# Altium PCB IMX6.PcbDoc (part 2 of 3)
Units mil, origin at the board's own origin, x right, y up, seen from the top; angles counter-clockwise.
Board outline 7950 x 5550 mil, 4 copper layers (Top Layer, GND, VCC, Bottom Layer), stack 30.634 mil thick; 238 components, 319 nets, 1015 pads, 404 vias.
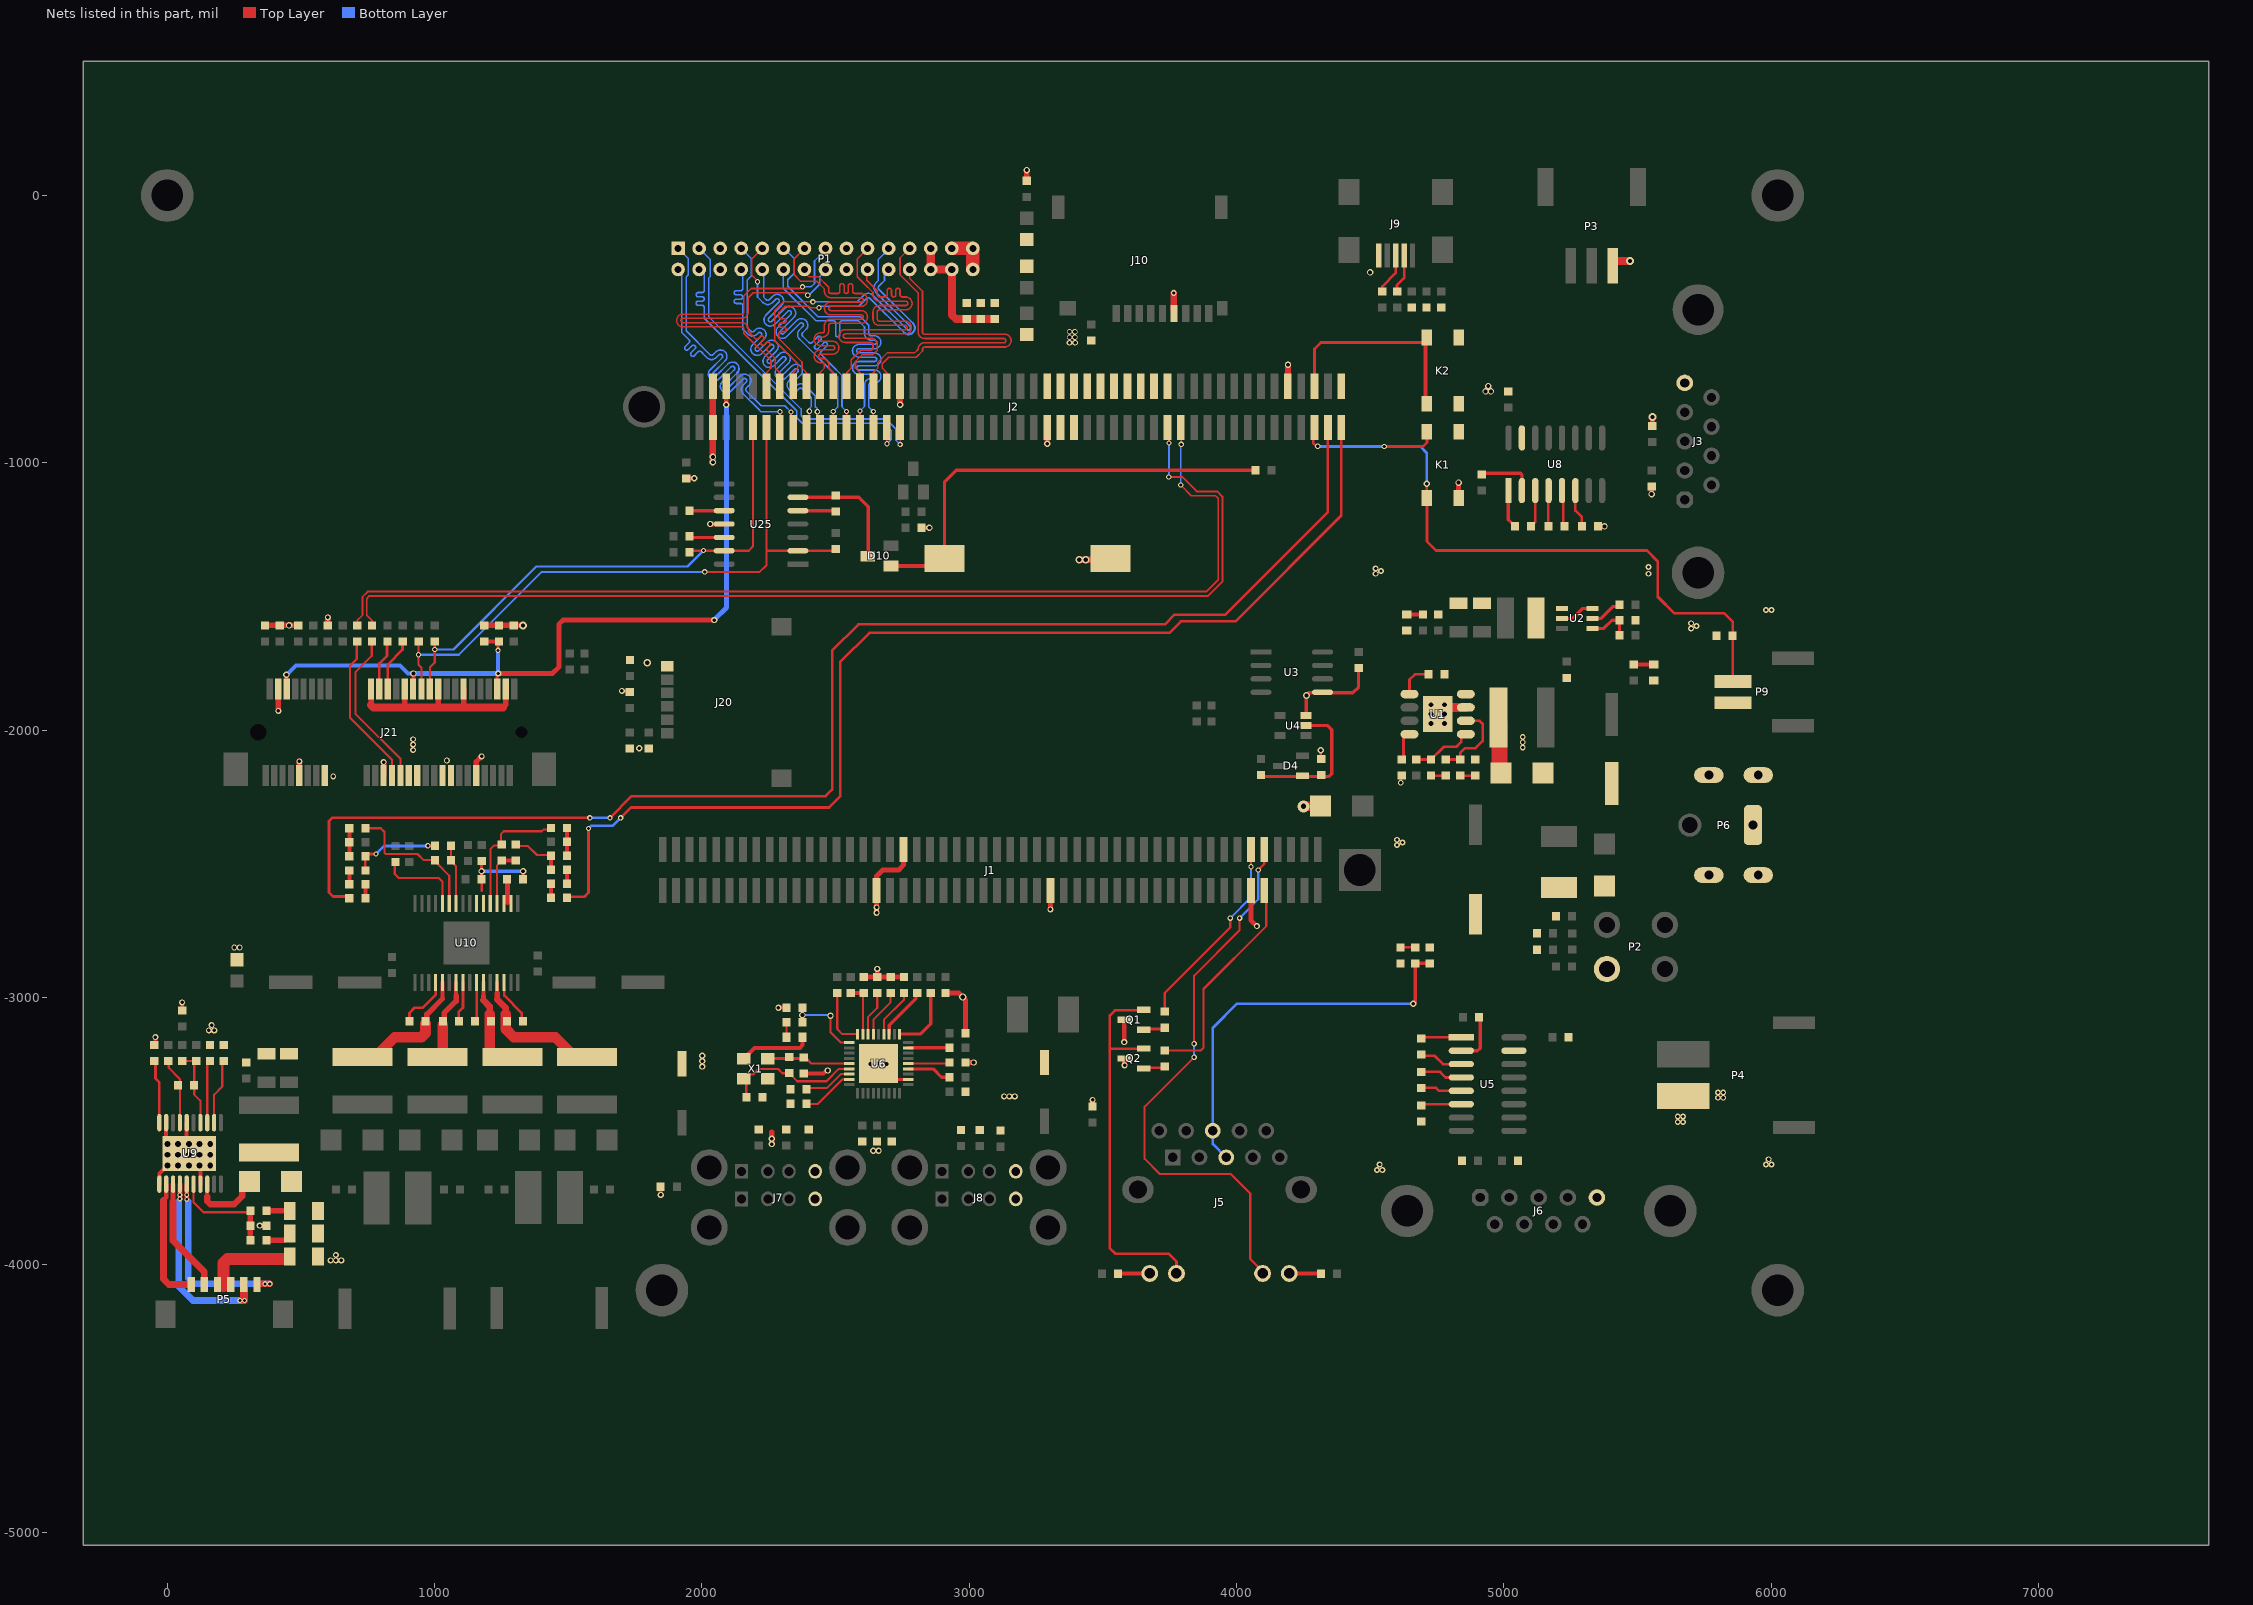
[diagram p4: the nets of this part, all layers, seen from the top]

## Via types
v1: diameter 20, hole 12, Top Layer to Bottom Layer, 138 vias
v2: diameter 22, hole 14, Top Layer to Bottom Layer, 54 vias
v3: diameter 24, hole 14, Top Layer to Bottom Layer, 53 vias
v4: diameter 22, hole 12, Top Layer to Bottom Layer, 39 vias
v5: diameter 23, hole 13, Top Layer to Bottom Layer, 38 vias
v6: diameter 22, hole 13, Top Layer to Bottom Layer, 21 vias
v7: diameter 30, hole 22, Top Layer to Bottom Layer, tented top, 15 vias
v8: diameter 22, hole 18, Top Layer to Bottom Layer, 6 vias
v9: diameter 25, hole 16, Top Layer to Bottom Layer, 5 vias
v10: diameter 24, hole 13, Top Layer to Bottom Layer, 5 vias
v11: diameter 20, hole 15, Top Layer to Bottom Layer, 5 vias
v12: diameter 30, hole 15, Top Layer to Bottom Layer, 4 vias
v13: diameter 18, hole 10, Top Layer to Bottom Layer, 4 vias
v14: diameter 20, hole 14, Top Layer to Bottom Layer, 4 vias
v15: diameter 28, hole 16, Top Layer to Bottom Layer, 3 vias
v16: diameter 26, hole 15, Top Layer to Bottom Layer, 3 vias
v17: diameter 45, hole 20, Top Layer to Bottom Layer, 1 vias
v18: diameter 28, hole 17, Top Layer to Bottom Layer, 1 vias
v19: diameter 25, hole 15, Top Layer to Bottom Layer, 1 vias
v20: diameter 28, hole 15, Top Layer to Bottom Layer, 1 vias
v21: diameter 18, hole 12, Top Layer to Bottom Layer, 1 vias
v22: diameter 30, hole 16, Top Layer to Bottom Layer, 1 vias
v23: diameter 25, hole 14, Top Layer to Bottom Layer, 1 vias

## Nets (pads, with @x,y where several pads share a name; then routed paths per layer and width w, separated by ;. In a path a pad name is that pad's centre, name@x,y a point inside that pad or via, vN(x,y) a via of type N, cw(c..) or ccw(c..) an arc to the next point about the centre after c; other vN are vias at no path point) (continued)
GND: BT1.2 C1.2 C2.2 C3.2 C5.2 C8.2 C10.1 C17.2 C18.2 C19.2 C20.1 C22.1 C23.2 C27.2 C29.2 C30.1 C31.1 C32.1 C34.1 C35.1 C36.2 C37.1 C38.1 C39.1 C40.1 C41.1 C42.1 C43.1 C44.1 C45.1 C46.1 C47.1 C48.1 C49.1 C50.1 C52.2 C53.1 C54.1 C55.2 C57.2 C58.1 C59.1 C60.1 C61.1 C62.1 C64.1 C86.2 C87.2 C88.2 C109.2 C110.2 C111.2 C112.2 C113.2 D1.A D3.K D5.K D7.A D8.K D16.1 D17.1 D18.2 D19.2 D20.2 D21.2 D22.2 D23.1 D24.2 D25.1 D26.2 D27.1 D28.2 D29.1 D30.1 D31.2 D32.2 D33.1 J1.33 J1.38 J1.59 J1.89 J2.5 J2.6 J2.34 J2.55 J2.92 J3.5 J6.5 J7.4 J7.8 J8.4 J8.8 J9.5 J10.6 J20.1 J21.4 J21.9 J21.15 J21.18 J21.21 J21.26 J21.27 J21.29 J21.34 J21.35 J21.37 J21.40 J21.43 J21.50 K1.1 K1.2 K2.1 K2.2 L2.1 L3.1 P1.5 P1.6 P1.17 P1.18 P1.25 P1.26 P1.28 P2.2 P3.3 P4.2 P6.1 P9.2 Q1.3 Q2.3 R1.1 R5.1 R15.2 R25.2 R26.2 R27.2 R28.1 R30.2 R37.1 R39.1 R43.2 R59.1 R87.1 R88.1 U1.7 U1.9 U2.1 U3.5 U4.3 U5.15 U6.11 U6.37 U8.15 U9.6 U9.9 U9.11 U9.17 U9.21 U25.11 X1.2 X1.4 | length 5501.4
  Top Layer w10: C22.1@4315,-2107 v3(4315,-2075) ; v1@4614,-2194 C8.2@4614,-2170 ; R1.1@4727,-2170 C10.1@4782,-2170
  Top Layer w12: C32.1@56,-3048 v5(56,-3018) ; v5(1701,-1853) 1733.71,-1853 1733.8,-1852.91 D32.2@1730.09,-1852.91 ; U6.37@2720.05,-3306.15 U6.11@2771.24,-3306.15 ; U4.3@4259.23,-1945.6 4260,-1944.83 4260,-1870 4270,-1860 4435,-1860 4456,-1839 C2.2@4456,-1768
  Top Layer w15: R43.2@-44,-3178 v5(-44,-3148) ; U9.11@-29.32,-3698 -29.32,-3658.32 U9.21@-14,-3643 ; U9.21@-3.72,-3528 U9.9@-3.72,-3468 ; U9.21@73.05,-3573.16 U9.6@73.05,-3468 ; U9.17@124.23,-3698 U9.21@124.23,-3624.34 ; v5(346,-3853) R37.1@371,-3853 ; v5(1846,-3738) C30.1@1846,-3708 ; X1.4@2156,-3228.2 2196.2,-3188 2366,-3188 2376,-3178 D5.K@2376,-3148 ; v5(2286,-3038) R30.2@2316,-3038 ; C39.1@2381,-3283.52 2455.48,-3283.52 2466,-3273 v3(2471,-3273)
  Top Layer w18: C18.2@1941,-1058 v3(1971,-1058) ; v3(2031,-1229) U25.11@2083.41,-1229 ; C31.1@2606,-2923 R25.2@2656,-2923 ; v5(2653.52,-2683) 2653.52,-2545.48 2676,-2523 2736,-2523 2753.52,-2505.48 J1.38@2753.52,-2446.23 ; v5(2656,-2893) R25.2@2656,-2923 ; R27.2@2756,-2923 R26.2@2706,-2923 R25.2@2656,-2923 ; C40.1@2821,-1243 v3(2851,-1243) ; C23.2@2911,-2983 2961,-2983 2986,-3008 C109.2@2986,-3133 ; C46.1@2986,-3243 v3(3016,-3243) ; v5(3303.52,-2670.52) J1.59@3303.52,-2599.77 ; C37.1@3461,-3408 v5(3461,-3383) ; v5(3579.58,-3166.58) Q1.3@3579.58,-3083 ; v5(3581,-3253) Q2.3@3581,-3229.42 ; J1.89@4053.52,-2599.77 4053.52,-2710.52 v5(4076,-2733) ; K1.2@4830.05,-1127.02 v3(4830.05,-1073.95) ; C55.2@5351,-1238 v3(5376,-1238) ; v3(5551.91,-1117.09) D18.2@5551.91,-1088.09 ; D19.2@5555.09,-862.91 v12@5555.09,-829
  Top Layer w20: C44.1@366,-1608 C50.1@421,-1608 R87.1@491,-1608 ; v5(415.8,-1927.8) J21.4@415.8,-1846.58 ; J21.9@494.54,-2169.42 v6(494.54,-2116.54) ; R88.1@601,-1608 v6(601,-1578) ; 762.72,-1906.72 J21.18@762.72,-1849.58 ; J21.21@809.5,-2171.5 v6(809.5,-2119.42) ; 888.72,-1918.72 J21.26@888.72,-1858.58 ; 1013.72,-1916.72 J21.34@1013.72,-1856.58 ; 1108.72,-1906.72 J21.40@1108.72,-1846.58 ; J21.43@1155.96,-2169.42 1155.96,-2118.04 v6(1176,-2098) ; C112.2@1186,-1608 C113.2@1241,-1608 C43.1@1296,-1608 v12(1331,-1608) ; 1256,-1916 1266,-1906 J21.50@1266,-1846.78 ; v5(2261,-3548) 2261,-3503 ; C111.2@3215,68 v3(3215,95) ; v3(3291.31,-928.51) J2.55@3291.31,-867.49
  Top Layer w22: v3(2741.31,-782.69) J2.34@2741.31,-713.94 ; J2.92@4191.31,-713.94 v3(4192,-633)
  Top Layer w24: v3(2041.31,-998.31) J2.6@2041.31,-713.94 ; v15(3411,-1363) BT1.2@3524.03,-1363
  Top Layer w25: J10.6@3765,-425 v4(3765,-365)
  Top Layer w30: 762.72,-1906.72 772,-1916 1256,-1916 ; P1.25@2855.88,-198 P1.26@2855.88,-276.74 P1.28@2934.62,-276.74 2934.62,-446.62 2951,-463 C52.2@2991,-463 C53.1@3043,-463 C54.1@3096,-463 ; D7.A@5145,-2160 D7.A@5145.74,-2160 ; P2.2@5385,-2895 P2.2@5385,-2893.35 ; P3.3@5424.48,-246 v12(5472,-246)
  Top Layer w35: v17@4250,-2284 D1.A@4314.26,-2284 ; U1.9@4777,-1915 U1.7@4857.31,-1915
  other v1: 4614,-2197
  other v2: 251,-2813 271,-2813 1046,-2113
  other v3: 1766,-2068 2041.31,-978 4931,-733 4951,-733 4941,-713 4499,-288
  other v4: 4525,-3645 4545,-3645 4535,-3625 5980,-3625 6000,-3625 5990,-3605 5650,-3465 5670,-3465 5650,-3445 5670,-3445 5800,-3375 5820,-3375 5800,-3355 5820,-3355 4600,-2430 4620,-2420 4600,-2410 920,-2074 5070,-2065 920,-2054 5070,-2045 920,-2034 5070,-2025 5700,-1620 5720,-1610 5700,-1600 5980,-1550 6000,-1550 4520,-1415 5540,-1415 4540,-1405 4520,-1395 5540,-1390 3375,-551 3396,-551
  other v5: 611,-3983 631,-3983 651,-3983 631,-3963 2641,-3573 2661,-3573 2261,-3528 3130,-3370 3150,-3370 3170,-3370 2001,-3258 2001,-3238 2001,-3218 156,-3123 176,-3123 166,-3103 2653.52,-2663
  other v6: 621,-2173
  other v7: 1,-3628 41,-3628 81,-3628 121,-3628 161,-3628 1,-3588 41,-3588 81,-3588 121,-3588 161,-3588 1,-3548 41,-3548 81,-3548 121,-3548 161,-3548
  other v8: 4727,-1975 4777,-1975 4727,-1940 4777,-1940 4727,-1905 4777,-1905
  other v12: 5555,-829
  other v14: 3375,-530 3395,-530 3375,-510 3395,-510
  other v15: 1796,-1748 3436,-1363
  other v16: 2631,-3248 2691,-3248 2661,-3247.09
  other v17: 4250,-2285
  other v18: 2976,-2998
  other v19: 456,-1608
  other v23: 4261,-1870
GVDD: C73.2 R45.1 R49.2 U10.6 U10.7 | length 289
  Top Layer w10: 1176,-2600.95 R49.2@1176,-2568 ; R49.2@1176.95,-2557.96 R49.2@1177,-2559
  Top Layer w12: R49.2@1176,-2558 C73.2@1176,-2488 ; R45.1@1331,-2558 v3(1331,-2528)
  Bottom Layer w12: v3(1176,-2528) v3(1331,-2528)
HDMI_CEC: J2.59
HDMI_CLK_N: J2.72
HDMI_CLK_P: J2.74
HDMI_D0_N: J2.62
HDMI_D0_P: J2.60
HDMI_D1_N: J2.68
HDMI_D1_P: J2.70
HDMI_D2_N: J2.64
HDMI_D2_P: J2.66
HDMI_HPD: J2.57
HDMI_TX_DDC_SCL: J2.58
HDMI_TX_DDC_SDA: J2.56
HPL: C78.1 J2.97 | length 5188.9
  Top Layer w10: C78.1@684,-2622 620,-2622 605,-2607 605,-2340 617,-2328 v1(1581,-2328) ; v1(1656,-2328) 1737,-2247 2462,-2247 2487,-2222 2487,-1702 2585,-1604 3732,-1604 3768,-1568 3958,-1568 4341.31,-1184.69 J2.97@4341.31,-867.49
  Bottom Layer w10: v1(1581,-2328) v1(1656,-2328)
HPR: C85.1 J2.99 | length 4249.6
  Top Layer w10: C85.1@1497,-2623 1561,-2623 1576,-2608 v1(1576,-2368) ; v1(1696,-2328) 1735,-2289 2476,-2289 2518,-2247 2518,-1744 2626,-1636 3749,-1636 3792,-1593 3995,-1593 4391.31,-1196.69 J2.99@4391.31,-867.49
  Bottom Layer w10: v1(1576,-2368) 1586,-2358 1666,-2358 v1(1696,-2328)
I2C3_SCL: J2.13 J21.30 R90.2 R112.1 U25.2 | length 2391.3
  Top Layer w8: R90.2@940,-1669 940,-1755 951.24,-1766.24 J21.30@951.24,-1846.58 ; v1(2011,-1408) 2216,-1408 2241.31,-1382.69 J2.13@2241.31,-867.49 ; 2241.31,-1329 R112.1@2495,-1329
  Bottom Layer w8: v1(940,-1718) 1091,-1718 1401,-1408 v1(2011,-1408)
I2C3_SDA: J2.11 J21.32 R89.2 R113.1 U25.13 | length 2036.7
  Top Layer w8: J21.32@982.73,-1846.58 982.73,-1765.27 1001,-1747 R89.2@1001,-1667 ; R113.1@1954,-1334 1959,-1329 U25.13@2083.41,-1329 2175,-1329 2191.31,-1312.69 J2.11@2191.31,-867.49
  Bottom Layer w8: v1(1001,-1698) 1071,-1698 1381,-1388 1946,-1388 v1(2006,-1328)
LED_ACT: J1.92 J5.13 | length 2092.6
  Top Layer w8: v1(3841,-3223) 3656,-3408 3656,-3603 3713,-3660 3978,-3660 4051,-3733 4051,-3978 J5.13@4091,-4018 ; v1(3841,-3173) 3841,-2918 4011,-2748 v1(4011,-2703) ; v1(4081,-2523) 4103.52,-2500.48 J1.92@4103.52,-2446.23
  Bottom Layer w8: v1(3841,-3223) v1(3841,-3173) ; v1(4011,-2703) 4081,-2633 v1(4081,-2523)
LED_LINK10_100: J1.91 R14.2 | length 837.8
  Top Layer w8: R14.2@3731,-3198 3866,-3198 3876,-3188 3876,-2968 4111,-2733 4111,-2607.25 J1.91@4103.52,-2599.77
LED_LINK1000: J1.90 R13.2 | length 740.4
  Top Layer w8: R13.2@3731,-3053 3731,-2983 3976,-2738 v1(3976,-2703) ; v1(4053.52,-2510.48) J1.90@4053.52,-2446.23
  Bottom Layer w8: v1(3976,-2703) 4053.52,-2625.48 v1(4053.52,-2510.48)
LVDS0_CLK_N: J2.14 P1.15 | length 1285.2
  Top Layer w6: 2185,-348.37 2157,-376.37 2157,-435.69 cw(c2149,-435.69) 2149,-443.69 1929.36,-443.69 ccw(c1929.36,-467.69) 1929.36,-491.69 2149,-491.69 cw(c2149,-499.69) 2157,-499.69 2157,-515 2258.31,-616.31 2258.31,-645.7 2241.31,-662.7 J2.14@2241.31,-713.94 ; 2185,-348 2370,-348 v1(2376,-342)
  Bottom Layer w6: v1(2376,-342) 2408.37,-342 2421,-329.37 2421,-245 P1.15@2460,-206
LVDS0_CLK_P: J2.16 P1.16 | length 1267.4
  Top Layer w6: J2.16@2291.31,-713.94 2291.31,-662.7 2274.31,-645.7 2274.31,-609.69 2246.31,-581.69 2245.07,-580.44 cw(c2250.73,-574.78) 2245.07,-569.13 2252.41,-561.79 ccw(c2246.75,-556.13) 2252.41,-550.47 ccw(c2246.75,-556.13) 2241.1,-550.47 2233.75,-557.81 cw(c2228.1,-552.16) 2222.44,-557.81 cw(c2228.1,-552.16) 2222.44,-546.5 2229.78,-539.16 ccw(c2224.12,-533.5) 2229.78,-527.85 ccw(c2224.12,-533.5) 2218.47,-527.85 2211.13,-535.19 cw(c2205.47,-529.53) 2199.81,-535.19 2173,-508.37 2173,-499.69 ccw(c2149,-499.69) 2149,-475.69 1929.36,-475.69 cw(c1929.36,-467.69) 1929.36,-459.69 2149,-459.69 ccw(c2149,-435.69) 2173,-435.69 2173,-383 2191.63,-364.37 2387.37,-364.37 v1(2396,-373)
  Bottom Layer w6: v1(2396,-373) 2400,-373 2441,-332 2441,-303.63 P1.16@2447.31,-297.31
LVDS0_TX0_N: J2.30 P1.23 | length 1315.5
  Top Layer w6: J2.30@2641.31,-713.94 2641.31,-662.7 2658.31,-645.7 2658.31,-623.37 2692.69,-589 2795,-589 2809,-575 cw(c2833,-575) 2833,-551 ; P1.23@2777.14,-198 2741,-234.14 2741,-297 2765.83,-321.83 2809,-365 2809,-511 ccw(c2833,-511) 2833,-535 3128.5,-535 ; 2834,-551 3129,-551 ccw(c3129,-543) 3137,-543 ccw(c3129,-543) 3129,-535
LVDS0_TX0_P: J2.32 P1.24 | length 1220.3
  Top Layer w6: J2.32@2691.31,-713.94 2691.31,-662.7 2674.31,-645.7 2674.31,-630 2699.31,-605 2801.63,-605 2825,-581.63 ; P1.24@2777.14,-276.74 2777.14,-310.51 2825,-358.37 2825,-511 ccw(c2833,-511) 2833,-519 3131.5,-519 ; 2825,-581 2825,-575 cw(c2833,-575) 2833,-567 3132.5,-567 ccw(c3132.5,-543) 3156.5,-543 ccw(c3132.5,-543) 3132.5,-519
LVDS0_TX1_N: J2.18 P1.21 | length 1288.4
  Top Layer w6: J2.18@2341.31,-713.94 2341.31,-662.7 2358.31,-645.7 2358.31,-629.31 2272,-543 2272,-431.37 2305.37,-398 2381,-398 v1(2415,-398)
  Bottom Layer w6: v1(2415,-398) 2444,-398 2580.37,-398 2605.26,-373.11 cw(c2622.23,-390.08) 2639.2,-373.11 2766.85,-500.76 ; P1.21@2697,-203 2659,-241 2659,-319.37 2650.51,-327.86 ccw(c2667.49,-344.83) 2650.51,-361.8 2778.16,-489.44
  Bottom Layer w8: 2766.85,-500.76 ccw(c2772.5,-495.1) 2778.14,-500.78 ; 2778.16,-500.76 ccw(c2772.5,-495.1) 2780.5,-495.1 ccw(c2772.5,-495.1) 2778.16,-489.44
LVDS0_TX1_P: J2.20 P1.22 | length 1275.4
  Top Layer w6: J2.20@2391.31,-713.94 2391.31,-662.7 2374.31,-645.7 2374.31,-622.69 2288,-536.37 2288,-517 cw(c2296,-517) 2296,-509 2306.96,-509 ccw(c2306.96,-501) 2314.96,-501 ccw(c2306.96,-501) 2306.96,-493 2296,-493 cw(c2296,-485) 2288,-485 cw(c2296,-485) 2296,-477 2306.96,-477 ccw(c2306.96,-469) 2314.96,-469 ccw(c2306.96,-469) 2306.96,-461 2296,-461 cw(c2296,-453) 2288,-453 2288,-438 2312,-414 2399.89,-414 2405.89,-420 v1(2438,-420)
  Bottom Layer w6: v1(2438,-420) 2444,-414 2587,-414 2616.57,-384.43 cw(c2622.23,-390.08) 2627.89,-384.43 2755.53,-512.07 ; P1.22@2683,-289 2683,-318 2670.31,-330.69 2661.83,-339.17 ccw(c2667.49,-344.83) 2661.83,-350.49 2789.47,-478.13
  Bottom Layer w8: 2755.53,-512.07 ccw(c2772.5,-495.1) 2796.5,-495.1 ccw(c2772.5,-495.1) 2789.47,-478.13
LVDS0_TX2_N: J2.26 P1.19 | length 1333.8
  Top Layer w6: J2.26@2541.31,-713.94 2541.31,-662.7 2558.31,-645.7 2558.31,-614.37 2593.69,-579 2634,-579 2640,-573 2640,-558 ccw(c2632,-558) 2632,-550 2536.46,-550 cw(c2536.46,-526) 2536.46,-502 2759.54,-502 ccw(c2759.54,-494) 2767.54,-494 ccw(c2759.54,-494) 2759.54,-486 2664,-486 cw(c2664,-462) 2640,-462 2640,-435.69 cw(c2664,-435.69) 2664,-411.69 2762,-411.69 ccw(c2762,-403.69) 2770,-403.69 ccw(c2762,-403.69) 2762,-395.69 2664,-395.69 cw(c2664,-371.69) 2640,-371.69 2640,-363 2605,-328 2581,-304 2581,-238 P1.19@2614,-205 ; P1.19@2605,-212.66 P1.19@2619.66,-198
LVDS0_TX2_P: J2.28 P1.20 | length 1278.5
  Top Layer w6: J2.28@2591.31,-674 2591.31,-662.7 2574.31,-645.7 2574.31,-621 2600.31,-595 2640.63,-595 2656,-579.63 2656,-558 ccw(c2632,-558) 2632,-534 2536.46,-534 cw(c2536.46,-526) 2536.46,-518 2759.54,-518 ccw(c2759.54,-494) 2783.54,-494 ccw(c2759.54,-494) 2759.54,-470 2664,-470 cw(c2664,-462) 2656,-462 2656,-435.69 cw(c2664,-435.69) 2664,-427.69 2762,-427.69 ccw(c2762,-403.69) 2786,-403.69 ccw(c2762,-403.69) 2762,-379.69 2757,-379.69 2749,-379.69 cw(c2749,-371.69) 2741,-371.69 2741,-355.28 ccw(c2733,-355.28) 2733,-347.28 ccw(c2733,-355.28) 2725,-355.28 2725,-371.69 cw(c2717,-371.69) 2717,-379.69 cw(c2717,-371.69) 2709,-371.69 2709,-355.28 ccw(c2701,-355.28) 2701,-347.28 ccw(c2701,-355.28) 2693,-355.28 2693,-371.69 cw(c2685,-371.69) 2685,-379.69 2664,-379.69 cw(c2664,-371.69) 2656,-371.69 2656,-356.37 2616.31,-316.69 P1.20@2616.31,-280.09
LVDS0_TX3_N: J2.22 P1.13 | length 1316.7
  Top Layer w6: P1.13@2380,-202 2345,-237 2345,-297 2368.69,-320.69 2400.31,-320.69 2429.06,-320.69 2458.31,-349.94 2458.31,-358.63 ccw(c2482.31,-358.63) 2482.31,-382.63 2595.31,-382.63 cw(c2595.31,-390.63) 2603.31,-390.63 cw(c2595.31,-390.63) 2595.31,-398.63 2482.31,-398.63 ccw(c2482.31,-422.63) 2482.31,-446.63 2595.31,-446.63 cw(c2595.31,-454.63) 2603.31,-454.63 cw(c2595.31,-454.63) 2595.31,-462.63 2482.31,-462.63 ccw(c2482.31,-486.63) 2458.31,-486.63 2458.31,-505.7 cw(c2450.31,-505.7) 2450.31,-513.7 2443.84,-513.7 ccw(c2443.84,-537.7) 2443.84,-561.7 2488.79,-561.7 cw(c2488.79,-569.7) 2496.79,-569.7 cw(c2488.79,-569.7) 2488.79,-577.7 2443.84,-577.7 ccw(c2443.84,-601.7) 2443.84,-625.7 2450.31,-625.7 cw(c2450.31,-633.7) 2458.31,-633.7 2458.31,-645.7 2441.31,-662.7 J2.22@2441.31,-713.94
LVDS0_TX3_P: J2.24 P1.14 | length 1304.6
  Top Layer w6: P1.14@2389.31,-293.69 2400.31,-304.69 2435.69,-304.69 2474.31,-343.31 2474.31,-358.63 ccw(c2482.31,-358.63) 2482.31,-366.63 2508,-366.63 ccw(c2508,-358.63) 2516,-358.63 2516,-337.65 cw(c2524,-337.65) 2524,-329.65 cw(c2524,-337.65) 2532,-337.65 2532,-358.63 ccw(c2540,-358.63) 2540,-366.63 ccw(c2540,-358.63) 2548,-358.63 2548,-337.65 cw(c2556,-337.65) 2556,-329.65 cw(c2556,-337.65) 2564,-337.65 2564,-358.63 ccw(c2572,-358.63) 2572,-366.63 2580,-366.63 2581,-366.63 2595.31,-366.63 cw(c2595.31,-390.63) 2619.31,-390.63 cw(c2595.31,-390.63) 2595.31,-414.63 2482.31,-414.63 ccw(c2482.31,-422.63) 2482.31,-430.63 2595.31,-430.63 cw(c2595.31,-454.63) 2619.31,-454.63 cw(c2595.31,-454.63) 2595.31,-478.63 2482.31,-478.63 ccw(c2482.31,-486.63) 2474.31,-486.63 2474.31,-505.7 cw(c2450.31,-505.7) 2450.31,-529.7 2443.84,-529.7 ccw(c2443.84,-537.7) 2443.84,-545.7 2488.79,-545.7 cw(c2488.79,-569.7) 2512.79,-569.7 cw(c2488.79,-569.7) 2488.79,-593.7 2443.84,-593.7 ccw(c2443.84,-601.7) 2443.84,-609.7 2450.31,-609.7 cw(c2450.31,-633.7) 2474.31,-633.7 2474.31,-645.7 2491.31,-662.7 J2.24@2491.31,-713.94
LVDS1_CLK_N: J2.33 P1.3 | length 1300.4
  Top Layer w6: v1(2741.31,-931.31) J2.33@2741.31,-867.49 2741,-867.17 J2.33@2746,-862.17
  Bottom Layer w6: P1.3@1989.74,-198 2031,-239.26 2031,-303 2025,-309 2025,-452.37 2371,-798.37 2371,-825 2382,-836 2688.28,-836 2724.66,-872.37 2724.66,-914.66 v1(2741.31,-931.31)
LVDS1_CLK_P: J2.31 P1.4 | length 1312.2
  Top Layer w6: J2.31@2691,-867.17 J2.31@2691.31,-867.49 ; v1(2692,-928.51) 2692,-846.17 J2.31@2696,-842.17
  Bottom Layer w6: P1.4@2009,-276 2009,-339 2009,-347 2009,-355 cw(c2001,-355) 2001,-363 1986.35,-363 ccw(c1986.35,-371) 1978.35,-371 ccw(c1986.35,-371) 1986.35,-379 2001,-379 cw(c2001,-387) 2009,-387 cw(c2001,-387) 2001,-395 1986.35,-395 ccw(c1986.35,-403) 1978.35,-403 ccw(c1986.35,-403) 1986.35,-411 2001,-411 cw(c2001,-419) 2009,-419 2009,-459 2355,-805 2355,-831.63 2375.37,-852 2681.66,-852 2708.66,-879 2708.66,-911.85 v1(2692,-928.51)
LVDS1_TX0_N: J2.29 P1.11 | length 1286.8
  Top Layer w6: J2.29@2641.31,-867.49 v1(2641.31,-808)
  Bottom Layer w6: P1.11@2310,-201 2345,-236 2345,-291 2320.7,-315.3 2320.7,-340.07 2433.63,-453 2592,-453 2624.31,-485.31 2624.31,-517 ccw(c2632.31,-517) 2632.31,-525 2645.58,-525 cw(c2645.58,-549) 2669.58,-549 cw(c2645.58,-549) 2645.58,-573 2587.05,-573 ccw(c2587.05,-581) 2587.05,-589 2645.58,-589 cw(c2645.58,-613) 2669.58,-613 cw(c2645.58,-613) 2645.58,-637 2587.05,-637 ccw(c2587.05,-645) 2587.05,-653 2645.58,-653 cw(c2645.58,-677) 2669.58,-677 cw(c2645.58,-677) 2645.58,-701 2632.31,-701 ccw(c2632.31,-709) 2624.31,-709 2624.31,-791 v1(2641.31,-808)
LVDS1_TX0_P: J2.27 P1.12 | length 1295.5
  Top Layer w6: J2.27@2591,-867.17 J2.27@2591.31,-867.49 v1(2591.31,-806) v1@2591.31,-803.69
  Bottom Layer w6: P1.12@2304.7,-276.74 2304.7,-315.3 2304.7,-346.7 2427,-469 2476,-469 2484,-469 2492,-469 cw(c2492,-477) 2500,-477 2500,-520.98 ccw(c2508,-520.98) 2508,-528.98 ccw(c2508,-520.98) 2516,-520.98 2516,-477 cw(c2524,-477) 2524,-469 2532,-469 2544,-469 2585.37,-469 2608.31,-491.94 2608.31,-517 ccw(c2632.31,-517) 2632.31,-541 2645.58,-541 cw(c2645.58,-549) 2653.58,-549 cw(c2645.58,-549) 2645.58,-557 2587.05,-557 ccw(c2587.05,-581) 2587.05,-605 2645.58,-605 cw(c2645.58,-613) 2653.58,-613 cw(c2645.58,-613) 2645.58,-621 2587.05,-621 ccw(c2587.05,-645) 2587.05,-669 2645.58,-669 cw(c2645.58,-677) 2653.58,-677 cw(c2645.58,-677) 2645.58,-685 2632.31,-685 ccw(c2632.31,-709) 2608.31,-709 2608.31,-789 v1(2591.31,-806)
LVDS1_TX1_N: J2.23 P1.9 | length 1243.2
  Top Layer w6: v1(2208,-323) 2208,-319 2187,-298 2187,-236.96 P1.9@2225.96,-198 ; v1(2491,-808) 2491,-867.17 J2.23@2491.31,-867.49
  Bottom Layer w6: v1(2208,-323) 2208,-366 2208,-380 2220.69,-392.69 2229.17,-401.17 ccw(c2246.14,-384.2) 2263.11,-401.17 2275.84,-388.44 cw(c2281.5,-394.1) 2287.15,-388.44 cw(c2281.5,-394.1) 2289.5,-394.1 cw(c2281.5,-394.1) 2287.15,-399.76 2239.08,-447.83 ; 2239.07,-447.84 ccw(c2256.04,-464.81) 2273.01,-481.78 ; 2273.02,-481.77 2321.09,-433.71 cw(c2326.75,-439.36) 2332.41,-433.7 ; 2332.43,-433.72 cw(c2326.75,-439.36) 2334.75,-439.36 cw(c2326.75,-439.36) 2332.42,-445.01 2284.33,-493.09 ccw(c2301.3,-510.07) 2318.27,-527.04 2366.35,-478.95 cw(c2372.01,-484.61) 2377.64,-478.93 cw(c2372.01,-484.61) 2380.01,-484.61 cw(c2372.01,-484.61) 2377.66,-490.27 2364.94,-502.99 ccw(c2381.91,-519.97) 2364.94,-536.94 2508,-680 2508,-791 v1(2491,-808)
LVDS1_TX1_P: J2.25 P1.10 | length 1298.1
  Top Layer w6: v1(2541,-808) 2541,-867.17 J2.25@2541.31,-867.49
  Bottom Layer w6: 2232,-367.37 P1.10@2232,-278 ; 2232,-360 2232,-381.37 2240.49,-389.86 ccw(c2246.14,-384.2) 2251.8,-389.86 2264.53,-377.13 cw(c2281.5,-394.1) 2305.5,-394.1 cw(c2281.5,-394.1) 2298.47,-411.07 2250.39,-459.15 ccw(c2256.04,-464.81) 2250.38,-470.47 ; 2250.4,-470.49 ccw(c2256.04,-464.81) 2261.68,-470.49 ; 2261.71,-470.46 2309.78,-422.38 cw(c2326.75,-439.36) 2350.75,-439.36 cw(c2326.75,-439.36) 2343.72,-456.33 2295.65,-504.4 ccw(c2301.3,-510.07) 2295.64,-515.72 ; 2295.66,-515.74 ccw(c2301.3,-510.07) 2306.93,-515.74 ; 2306.96,-515.72 2355.04,-467.64 cw(c2372.01,-484.61) 2396.01,-484.61 cw(c2372.01,-484.61) 2388.98,-501.58 2376.25,-514.31 ccw(c2381.91,-519.97) 2376.25,-525.62 2400.63,-550 ccw(c2406.28,-544.34) 2411.94,-550 2433.01,-528.93 cw(c2438.67,-534.59) 2444.32,-528.93 cw(c2438.67,-534.59) 2444.32,-540.25 2423.25,-561.31 ccw(c2428.91,-566.97) 2423.25,-572.63 ccw(c2428.91,-566.97) 2434.57,-572.63 2455.64,-551.56 cw(c2461.29,-557.22) 2466.95,-551.56 cw(c2461.29,-557.22) 2466.95,-562.87 2445.88,-583.94 ccw(c2451.54,-589.6) 2445.88,-595.25 2483.81,-633.19 2524,-673.37 2524,-791 v1(2541,-808)
LVDS1_TX2_N: J2.21 P1.7 | length 1287.1
  Top Layer w6: v1(2432,-809) 2432,-858.17 J2.21@2441.31,-867.49
  Bottom Layer w6: P1.7@2153,-204 2185,-236 2185,-301 2169,-317 2169,-493.37 2183.31,-507.69 ccw(c2188.97,-502.03) 2194.63,-507.69 2199.17,-503.14 cw(c2216.14,-520.11) 2240.14,-520.11 cw(c2216.14,-520.11) 2233.11,-537.08 2201.4,-568.79 ccw(c2207.05,-574.46) 2201.38,-580.09 ccw(c2207.05,-574.46) 2212.69,-580.13 ; 2212.72,-580.11 2244.43,-548.4 cw(c2261.4,-565.37) 2285.4,-565.37 cw(c2261.4,-565.37) 2278.37,-582.34 2246.66,-614.05 ccw(c2252.31,-619.71) 2246.63,-625.35 ccw(c2252.31,-619.71) 2257.95,-625.39 ; 2257.97,-625.36 2289.68,-593.65 cw(c2306.65,-610.62) 2330.65,-610.62 cw(c2306.65,-610.62) 2323.62,-627.59 2291.91,-659.31 ccw(c2297.56,-664.97) 2291.91,-670.62 ; 2291.93,-670.64 ccw(c2297.56,-664.97) 2303.22,-670.62 2334.94,-638.91 cw(c2351.91,-655.88) 2375.91,-655.88 cw(c2351.91,-655.88) 2368.88,-672.85 2337.17,-704.56 ccw(c2342.82,-710.22) 2337.14,-715.86 ; 2337.16,-715.88 ccw(c2342.82,-710.22) 2348.47,-715.88 2353.02,-711.33 cw(c2369.99,-728.3) 2386.96,-711.33 2424.31,-748.69 2424.31,-790.31 2432,-798 v1(2432,-809)
LVDS1_TX2_P: J2.19 P1.8 | length 1272
  Top Layer w6: J2.19@2391.31,-867.49 2402,-856.8 v1(2402,-807)
  Bottom Layer w6: P1.8@2153,-301 2153,-317 2153,-332 2153,-340 2153,-348 cw(c2145,-348) 2145,-356 2128.67,-356 ccw(c2128.67,-364) 2120.67,-364 ccw(c2128.67,-364) 2128.67,-372 2145,-372 cw(c2145,-380) 2153,-380 cw(c2145,-380) 2145,-388 2128.67,-388 ccw(c2128.67,-396) 2120.67,-396 ccw(c2128.67,-396) 2128.67,-404 2145,-404 cw(c2145,-412) 2153,-412 2153,-483 2153,-500 2172,-519 ccw(c2188.97,-502.03) 2205.94,-519 2210.48,-514.46 cw(c2216.14,-520.11) 2221.78,-514.44 cw(c2216.14,-520.11) 2224.14,-520.11 cw(c2216.14,-520.11) 2221.81,-525.76 ; 2221.79,-525.78 2190.09,-557.48 ccw(c2207.05,-574.46) 2224.02,-591.43 ; 2224.03,-591.42 2255.73,-559.72 cw(c2261.4,-565.37) 2267.05,-559.71 ; 2267.05,-571.03 2235.34,-602.73 ccw(c2252.31,-619.71) 2269.28,-636.68 ; 2267.06,-571.02 ccw(c2261.4,-565.37) 2269.4,-565.37 ccw(c2261.4,-565.37) 2267.07,-559.73 ; 2269.29,-636.67 2300.99,-604.97 cw(c2306.65,-610.62) 2312.31,-604.97 ; 2312.33,-604.99 cw(c2306.65,-610.62) 2314.65,-610.62 cw(c2306.65,-610.62) 2312.31,-616.28 2280.59,-648 ccw(c2297.56,-664.97) 2314.53,-681.94 2346.24,-650.23 ; 2346.25,-650.22 cw(c2351.91,-655.88) 2357.54,-650.2 cw(c2351.91,-655.88) 2359.91,-655.88 cw(c2351.91,-655.88) 2357.57,-661.53 2325.85,-693.24 ccw(c2342.82,-710.22) 2359.79,-727.19 2364.33,-722.65 cw(c2369.99,-728.3) 2375.65,-722.65 2408.31,-755.31 2408.31,-791 2402,-797.31 v1(2402,-807)
LVDS1_TX3_N: J2.17 P1.1 | length 1271.7
  Top Layer w6: v1(2333,-810) 2333,-855.8 2343,-865.8 J2.17@2341.31,-867.49 J2.17@2341,-867.17
  Bottom Layer w6: P1.1@1929,-216 1949,-236 1949,-297 1941,-305 1941,-506.37 2030.31,-595.69 ccw(c2035.97,-590.03) 2041.63,-595.69 2052.36,-584.95 cw(c2069.33,-601.93) 2093.33,-601.93 cw(c2069.33,-601.93) 2086.3,-618.9 2042.22,-662.98 ccw(c2047.87,-668.64) 2042.21,-674.3 ; 2042.23,-674.32 ccw(c2047.87,-668.64) 2053.5,-674.32 ; 2053.53,-674.29 2097.61,-630.21 cw(c2114.58,-647.18) 2138.58,-647.18 ; 2087.46,-719.55 cw(c2093.12,-713.9) 2087.46,-708.25 2131.55,-664.15 ; 2087.48,-719.57 ccw(c2093.12,-713.9) 2098.76,-719.57 ; 2098.79,-719.55 2142.87,-675.46 cw(c2159.84,-692.44) 2183.84,-692.44 cw(c2159.84,-692.44) 2176.81,-709.41 2166.08,-720.14 ccw(c2171.74,-725.79) 2166.08,-731.45 2221.63,-787 2310,-787 v1(2333,-810)
  Bottom Layer w8: 2131.55,-664.15 ccw(c2114.58,-647.18) 2138.58,-647.18
LVDS1_TX3_P: J2.15 P1.2 | length 1279.9
  Top Layer w6: J2.15@2291.31,-867.49 J2.15@2292,-866.8 ; v1(2292,-809) J2.15@2292,-866.8 ; J2.15@2298,-860.8 J2.15@2292,-866.8
  Bottom Layer w6: P1.2@1925,-295 1925,-513 1940.5,-528.5 1946.16,-534.16 1951.81,-539.81 cw(c1946.16,-545.47) 1951.81,-551.13 1937.79,-565.15 ccw(c1943.45,-570.81) 1937.79,-576.47 ccw(c1943.45,-570.81) 1949.1,-576.47 1963.13,-562.44 cw(c1968.78,-568.1) 1974.44,-562.44 cw(c1968.78,-568.1) 1974.44,-573.75 1960.42,-587.78 ccw(c1966.07,-593.44) 1960.42,-599.09 ccw(c1966.07,-593.44) 1971.73,-599.09 1985.75,-585.07 cw(c1991.41,-590.73) 1997.07,-585.07 2009.5,-597.5 2019,-607 ccw(c2035.97,-590.03) 2052.94,-607 2063.67,-596.27 cw(c2069.33,-601.93) 2074.97,-596.25 ; 2074.99,-596.27 cw(c2069.33,-601.93) 2077.33,-601.93 cw(c2069.33,-601.93) 2074.99,-607.58 2030.9,-651.67 ccw(c2047.87,-668.64) 2064.84,-685.61 2108.92,-641.53 ; 2076.15,-696.93 ccw(c2093.12,-713.9) 2110.09,-730.87 2154.18,-686.78 cw(c2159.84,-692.44) 2165.48,-686.76 ; 2076.16,-696.92 2120.23,-652.84 ccw(c2114.58,-647.18) 2122.58,-647.18 ccw(c2114.58,-647.18) 2120.26,-641.54 ; 2108.95,-641.5 cw(c2114.58,-647.18) 2120.24,-641.52 ; 2165.5,-686.78 cw(c2159.84,-692.44) 2167.84,-692.44 cw(c2159.84,-692.44) 2165.5,-698.09 2154.76,-708.82 ccw(c2171.74,-725.79) 2154.76,-742.76 2210.31,-798.31 2221,-809 v1(2292,-809)
MIC: J2.100
MINIPCIE1V5: C112.1 C113.1 J2.8 J21.6 J21.28 J21.48 | length 3040.6
  Top Layer w12: J21.28@919.74,-1846.58 J21.28@921,-1845.32 ; C112.1@1186,-1673 C112.1@1191,-1668 ; J21.48@1234,-1844 1234,-1791.5 v10(1237.5,-1788) v10@1246,-1788 ; v1(1237.5,-1701.5) 1237.5,-1671.5 C113.1@1241,-1668 ; J2.8@2091,-714.26 J2.8@2091.31,-713.94
  Top Layer w15: J21.6@446,-1845.28 v3(446,-1793) ; J21.28@921,-1845.32 v3(921,-1788) ; C112.1@1191,-1668 C113.1@1241,-1668
  Top Layer w18: v10@1246,-1788 1441,-1788 1465,-1764 1465,-1604 1481,-1588 v10(2046,-1588) ; v10(2091,-783) J2.8@2091,-714.26
  Bottom Layer w12: v3(921,-1788) v3@926,-1788
  Bottom Layer w15: v3(446,-1793) 481,-1758 871,-1758 901,-1788 v3(921,-1788) ; v10(1237.5,-1788) v1(1237.5,-1701.5)
  Bottom Layer w18: v3@926,-1788 v10(1237.5,-1788) ; v10@2048.5,-1585.5 2092,-1542 v10@2092,-783
NetBT1_1: BT1.1 D10.1 R119.2 | length 1635.2
  Top Layer w12: BT1.1@2906.98,-1368 2906.98,-1072.02 2951,-1028 R119.2@4061,-1028
  Top Layer w15: D10.1@2722,-1386.06 BT1.1@2888.92,-1386.06
NetC4_1: C4.1 D7.K L1.1 U1.8 | length 181.7
  Top Layer w60: D7.K@4983.26,-2155 L1.1@4983.26,-1973.26
NetC4_2: C4.2 U1.1 | length 133.4
  Top Layer w10: U1.1@4646.69,-1865 4646.69,-1811.32 4667,-1791 C4.2@4718,-1791
NetC6_1: C6.1 U8.1 | length 123.7
  Top Layer w10: 5016,-1213 C6.1@5041,-1238
  Top Layer w12: 5016,-1213 U8.1@5016,-1124.67
NetC6_2: C6.2 U8.3 | length 140.8
  Top Layer w10: C6.2@5101,-1238 5116.91,-1222.09 U8.3@5116.91,-1103.76
NetC7_1: C7.1 U8.2 | length 216.6
  Top Layer w8: C7.1@4916,-1048 C7.1@4925.09,-1038.91
  Top Layer w12: C7.1@4925.09,-1038.91 5061.91,-1038.91 5066.91,-1043.91 U8.2@5066.91,-1103.76
NetC8_1: C8.1 U1.4 | length 90
  Top Layer w10: C8.1@4624,-2111 U1.4@4624,-2021
NetC9_1: C9.1 R5.2 | length 56
  Top Layer w10: C9.1@4836,-2170 R5.2@4892,-2170
NetC9_2: C9.2 C10.2 U1.6 | length 313.5
  Top Layer w10: C10.2@4782,-2110 C9.2@4836,-2110 4836,-2085 4854,-2067 4894,-2067 4920,-2041 4920,-1976 4909,-1965 U1.6@4857.31,-1965
NetC19_1: C19.1 J5.5 J5.6 R12.2 | length 1492.8
  Top Layer w12: v3@4668,-3016 R12.2@4668,-2872 ; R12.2@4668.04,-2871.68 C19.1@4723.86,-2871.68
  Bottom Layer w10: J5.6@3961,-3598 3911,-3548 J5.5@3911,-3498 3911,-3113 4001,-3023 v3(4661,-3023)
NetC20_2: C20.2 R12.1 | length 53.9
  Top Layer w10: C20.2@4614.18,-2811.68 R12.1@4668.04,-2811.68
NetC22_2: C22.2 D4.1 R18.1 U4.2 | length 525.4
  Top Layer w12: R18.1@4096,-2173 4346,-2173 4356,-2163 4356,-1998 4341,-1983 U4.2@4266,-1983
NetC24_1: C24.1 U5.1 | length 140.2
  Top Layer w10: C24.1@4700.09,-3148.91 U5.1@4840.24,-3148.91
NetC24_2: C24.2 U5.3 | length 162
  Top Layer w10: C24.2@4691,-3218 4741,-3218 4771.91,-3248.91 U5.3@4840.24,-3248.91
NetC25_1: C25.1 U5.2 | length 185.8
  Top Layer w12: U5.2@4840.24,-3198.91 4901,-3198.91 4911,-3188.91 C25.1@4911,-3078
NetC27_1: C27.1 U5.6 | length 145.2
  Top Layer w10: C27.1@4695.09,-3398.91 U5.6@4840.24,-3398.91
NetC28_1: C28.1 U5.4 | length 157.9
  Top Layer w10: C28.1@4691,-3278 4761,-3278 4781.91,-3298.91 U5.4@4840.24,-3298.91
NetC28_2: C28.2 U5.5 | length 153.8
  Top Layer w10: C28.2@4691,-3338 4746,-3338 4756.91,-3348.91 U5.5@4840.24,-3348.91
NetC31_2: C31.2 R24.2 U6.26 | length 192.9
  Top Layer w8: U6.26@2601.95,-3136.86 C31.2@2601.95,-2993.95
  Top Layer w15: R24.2@2556,-2983 C31.2@2606,-2983
NetC38_2: C38.2 R31.1 U6.33 X1.1 | length 482.5
  Top Layer w8: X1.1@2171,-3288 2191,-3288 2211.65,-3267.35 2285.35,-3267.35 2301,-3283 R31.1@2326,-3283 ; R31.1@2335.96,-3283.32 R31.1@2335.96,-3273.04 ; R31.1@2336,-3293 2356,-3313 2466,-3313 2512.22,-3266.78 U6.33@2550.76,-3266.78
  Top Layer w10: C38.2@2166,-3373 X1.1@2166,-3313
NetC39_2: C39.2 R31.2 U6.32 X1.3 | length 302.4
  Top Layer w8: C39.2@2386,-3233 C39.2@2391,-3233 ; C39.2@2391,-3228 2410.09,-3247.09 U6.32@2550.76,-3247.09
  Top Layer w10: X1.3@2246.55,-3228.2 C39.2@2376.32,-3228.2
NetC45_2: C45.2 U6.34 | length 185
  Top Layer w8: C45.2@2396.48,-3339.02 2419.98,-3339.02 ; 2411,-3339.02 2467.13,-3339.02 2519.68,-3286.46 U6.34@2550.76,-3286.46
NetC46_2: C46.2 U6.14 | length 164.2
  Top Layer w8: U6.14@2771.24,-3247.09 C46.2@2935.41,-3247.09
NetC52_1: C52.1 C53.2 C54.2 L4.2 L5.1 P1.27 P1.29 P1.30 | length 157.5
  Top Layer w50: P1.27@2934.62,-198 P1.29@3013.36,-198 P1.30@3013.36,-276.74
NetC55_1: C55.1 U8.6 | length 144.2
  Top Layer w10: U8.6@5266.91,-1103.76 5266.91,-1178.91 5291,-1203 C55.1@5291,-1238
NetC56_1: C56.1 U8.4 | length 134.6
  Top Layer w10: C56.1@5166,-1238 5166,-1104.67 U8.4@5166.91,-1103.76
NetC56_2: C56.2 U8.5 | length 125.2
  Top Layer w10: C56.2@5221,-1243 U8.5@5221,-1117.84
NetC60_2: C60.2 C61.2 C62.2 C63.2 D11.K P5.3 P5.4 R38.2 | length 457.2
  Top Layer w20: C63.2@371,-3908 436,-3908 ; R38.2@381,-3798 431,-3798
  Top Layer w40: C60.2@447.85,-3978 C60.2@457.85,-3968
  Top Layer w45: 211,-4078 211,-3993 226,-3978 C60.2@447.85,-3978
NetC63_1: C63.1 R37.2 R38.1 U9.16 | length 422.5
  Top Layer w8: U9.16@98.64,-3698 98.64,-3765.64 136,-3803 316,-3803 R38.1@321,-3808
  Top Layer w20: C63.1@311,-3908 R38.1@311,-3793
NetC64_2: C64.2 U9.2 | length 242.7
  Top Layer w8: U9.2@175.41,-3468 175.41,-3363.59 206,-3333 C64.2@206,-3238
NetC67_1: C67.1 R47.1 RS1.1 | length 197.1
  Top Layer w8: C67.1@1302,-2433 1349,-2433 1383,-2467 RS1.1@1437,-2467
  Top Layer w15: R47.1@1436,-2516 RS1.1@1436,-2468
NetC67_2: C67.2 C69.1 U10.4 | length 211.4
  Top Layer w8: U10.4@1234.23,-2648 1234.23,-2505.77 C69.1@1252,-2488
  Top Layer w15: C69.1@1251,-2488 1252,-2488 C67.2@1295,-2488
NetC68_1: C68.1 U10.30 | length 151.9
  Top Layer w10: U10.30@1261,-2968 1261,-2993 1326,-3058 C68.1@1326,-3093
NetC68_2: C68.2 L7.1 U10.29 | length 536.4
  Top Layer w15: 1234.23,-2983.37 U10.29@1234.23,-2943.28
  Top Layer w20: 1234.23,-3006.23 1234.23,-2983.37
  Top Layer w25: 1234.23,-3006.23 1266,-3038 1266,-3063
  Top Layer w40: 1266,-3063 1266,-3118 1296,-3148 1451,-3148 1526,-3223 L7.1@1571,-3223
NetC69_2: C69.2 C71.2 U10.5 | length 492.8
  Top Layer w8: U10.5@1208.64,-2648 1208.64,-2445.36 1222,-2432 C69.2@1255,-2432 ; C69.2@1249,-2431 1249,-2388 1259,-2378 1401,-2378 1407,-2372 1432,-2372 C71.2@1436,-2368
NetC71_1: C71.1 R48.1 RS1.2 | length 108
  Top Layer w10: RS1.2@1496,-2476 RS1.2@1496,-2468
  Top Layer w15: RS1.2@1496,-2468 R48.1@1496,-2418 C71.1@1496,-2368
NetC74_1: C74.1 U10.26 | length 133.3
  Top Layer w10: C74.1@1157.46,-3076.54 U10.26@1157.46,-2943.28
NetC74_2: C74.2 L8.1 U10.27 | length 269.2
  Top Layer w15: 1183.05,-2994.21 U10.27@1183.05,-2943.28
  Top Layer w20: 1183.05,-3010.05 1183.05,-2994.21
  Top Layer w25: 1183.05,-3010.05 1206,-3033 1206,-3063
  Top Layer w40: L8.1@1206,-3203 1206,-3063
NetC75_1: C75.1 U10.24 | length 151.1
  Top Layer w10: C75.1@1091,-3088 1091,-3053 1106.28,-3037.72 U10.24@1106.28,-2943.28
NetC75_2: C75.2 L9.1 U10.23 | length 291.5
  Top Layer w8: L9.1@1011,-3223 L9.1@1031,-3203
  Top Layer w15: 1080.68,-2993.31 U10.23@1080.68,-2943.28
  Top Layer w20: C75.2@1036,-3088 1036,-3058 1080.68,-3013.32 1080.68,-2993.31
  Top Layer w40: L9.1@1031,-3203 C75.2@1031,-3103
NetC77_1: C77.1 R52.1 RS2.1 | length 326.9
  Top Layer w10: R52.1@741,-2513 741,-2468 746,-2463 v1(781,-2463) ; v1@975,-2433 1007,-2433 C77.1@1008,-2434
  Bottom Layer w10: v1(781,-2463) 811,-2433 v1@975,-2433
  other v1: 975,-2432
NetC77_2: C77.2 C79.1 U10.10 | length 227.7
  Top Layer w8: C79.1@1062,-2497 C77.2@1062,-2427 ; C79.1@1067,-2496 1080.68,-2509.68 U10.10@1080.68,-2648
NetC78_2: C78.2 R51.1 | length 49
  Top Layer w15: C78.2@741,-2622 R51.1@741,-2573
NetC79_2: C79.2 C81.2 U10.11 | length 522.3
  Top Layer w8: C81.2@746.5,-2374.5 754,-2367 799,-2367 812.88,-2380.88 812.88,-2457.88 818,-2463 936,-2463 959,-2486 998,-2486 C79.2@1001,-2489 ; C79.2@1009,-2498 1055.09,-2544.09 U10.11@1055.09,-2648
NetC81_1: C81.1 R53.1 RS2.2 | length 104
  Top Layer w15: RS2.2@681,-2477 681,-2473 681,-2423 C81.1@681,-2373
NetC82_1: C82.1 U10.20 | length 202.9
  Top Layer w10: C82.1@906,-3088 906,-3058 926,-3038 956,-3038 1003.91,-2990.09 U10.20@1003.91,-2943.28
NetC82_2: C82.2 L10.1 U10.21 | length 476.2
  Top Layer w15: 1029.5,-3004.5 U10.21@1029.5,-2943.28
  Top Layer w20: C82.2@971,-3088 971,-3063 1029.5,-3004.5
  Top Layer w40: L10.1@731,-3223 776,-3223 851,-3148 951,-3148 966,-3133 C82.2@966,-3098
NetC85_2: C85.2 R46.1 | length 57
  Top Layer w15: C85.2@1436,-2625 1436,-2623 R46.1@1436,-2568
NetD2_K: D2.K F1.1
NetD3_A: D3.A R9.1 | length 60
  Top Layer w15: D3.A@4637,-1567 R9.1@4697,-1567
NetD5_A: D5.A R29.1 | length 55
  Top Layer w8: D5.A@2316,-3148 R29.1@2316,-3093
NetD8_A: D8.A R3.2 | length 65
  Top Layer w15: R3.2@5485,-1755 D8.A@5550,-1755
NetD10_3: D10.3 R116.2 U25.6 | length 447.5
  Top Layer w12: U25.6@2374,-1129 2587,-1129 2622,-1164 D10.3@2622,-1349
NetD11_A: D11.A L6.2 U9.18 | length 277.9
  Top Layer w15: 149.82,-3745.36 U9.18@149.82,-3698
  Top Layer w25: 149.82,-3745.36 149.82,-3761.82 161,-3773 251,-3773 281,-3743 281,-3714.26 D11.A@307.26,-3688
NetJ5_11: J5.11 R10.1 | length 114
  Top Layer w15: R10.1@3561,-4032.07 J5.11@3674.98,-4032.07
NetJ5_12: J5.12 Q1.2 Q2.2 | length 1427.9
  Top Layer w10: 3531,-3190.94 Q2.2@3648.42,-3190.94 ; Q1.2@3643.42,-3048 3545.21,-3048 3526,-3067.21 3526,-3938 3546,-3958 3746,-3958 3774.98,-3986.98 J5.12@3774.98,-4032.07
NetJ5_14: J5.14 R11.1 | length 113
  Top Layer w15: J5.14@4197.02,-4032.07 R11.1@4310.07,-4032.07
NetJ9_2: J9.2 R33.1 | length 146
  Top Layer w10: R33.1@4600,-360 4600,-335 4626.5,-308.5 J9.2@4626.5,-225
NetJ9_3: J9.3 R34.1 | length 155.7
  Top Layer w10: R34.1@4545,-360 4545,-340 4595,-290 J9.3@4595,-225
NetJ21_20: J21.20 R104.2 | length 190.3
  Top Layer w10: J21.20@793.76,-1846.58 793.76,-1750.24 822,-1722 R104.2@822,-1668
NetJ21_22: J21.22 R105.2 | length 200.3
  Top Layer w10: J21.22@825.25,-1846.58 825.25,-1753.75 880,-1699 R105.2@880,-1669
NetL11_2: L11.2 U2.2 U2.6 | length 129.7
  Top Layer w12: U2.2@5216.91,-1582 5257,-1582 5294.4,-1544.6 U2.6@5331.09,-1544.6
NetP5_1: P5.1 U9.12 | length 471.5
  Top Layer w18: -14,-3758 -3.72,-3747.72 U9.12@-3.72,-3698
  Top Layer w25: -14,-3758 -14,-4053 6,-4073 P5.1@89.94,-4073
NetP5_2: P5.2 U9.13 | length 423.6
  Top Layer w18: 21.87,-3763 U9.13@21.87,-3698
  Top Layer w25: 21.87,-3763 21.87,-3908.87 139.15,-4026.15 P5.2@139.15,-4073
NetP5_5: P5.5 U9.14 | length 698.7
  Top Layer w18: v13(47.46,-3753) v13(47.46,-3738) U9.14@47.46,-3698
  Top Layer w30: v1@286.79,-4130.79 P5.5@286.79,-4073
  Bottom Layer w25: 43,-3762 43,-4080 96,-4133 v1(272,-4133) v1(289,-4133)
NetP5_6: P5.6 U9.15 | length 703.2
  Top Layer w18: v13(73.05,-3755.05) v13(73.05,-3738) U9.15@73.05,-3698
  Top Layer w25: P5.6@338,-4071 v1(384,-4071)
  Bottom Layer w25: 79,-3763 79,-4049 101,-4071 v1(384,-4071)
  other v1: 366,-4071
NetQ1_1: Q1.1 R13.1 | length 76.2
  Top Layer w10: Q1.1@3649.82,-3118 R13.1@3726,-3118
NetQ2_1: Q2.1 R14.1 | length 71.2
  Top Layer w10: Q2.1@3654.82,-3263 R14.1@3726,-3263
NetR1_2: R1.2 R2.1 U1.5 | length 225.3
  Top Layer w10: R2.1@4669,-2110 R1.2@4727,-2110 4775,-2062 4822,-2062 4840,-2044 U1.5@4840,-2017
NetR4_2: R4.2 U2.5 | length 120.6
  Top Layer w12: U2.5@5331.09,-1582 5363,-1582 5408,-1537 R4.2@5433,-1537
NetR19_1: R19.1 U6.27 | length 218.8
  Top Layer w8: R19.1@2505.96,-2983.32 2505.96,-3117.96 2524.86,-3136.86 U6.27@2582.26,-3136.86
NetR20_2: R20.2 U6.13 | length 167.7
  Top Layer w12: U6.13@2771.24,-3266.78 2864.78,-3266.78 2896.04,-3298.04 R20.2@2926,-3298
NetR21_2: R21.2 U6.17 | length 154.8
  Top Layer w12: U6.17@2771.24,-3188.04 R21.2@2926,-3188
NetR22_2: R22.2 U6.19 | length 247.7
  Top Layer w12: U6.19@2739.74,-3136.86 2817.14,-3136.86 2856.04,-3097.96 R22.2@2856.04,-2982.68
NetR23_2: R23.2 U6.21 | length 190.5
  Top Layer w12: U6.21@2700.37,-3136.86 2700.37,-3103.63 2801,-3003 R23.2@2801,-2988
NetR25_1: R25.1 U6.25 | length 167.8
  Top Layer w8: U6.25@2621.63,-3136.86 2621.63,-3072.37 2655.96,-3038.04 R25.1@2655.96,-2983.32
NetR26_1: R26.1 U6.24 | length 180.3
  Top Layer w8: U6.24@2641.32,-3136.86 2641.32,-3082.68 2705.96,-3018.04 R26.1@2705.96,-2983.32
NetR27_1: R27.1 U6.22 | length 184.7
  Top Layer w8: U6.22@2680.68,-3136.86 2680.68,-3083.32 2755.96,-3008.04 R27.1@2755.96,-2983.32
NetR28_2: R28.2 U6.35 | length 197.8
  Top Layer w8: R28.2@2391,-3398 2433.6,-3398 2525.28,-3306.32 2550.59,-3306.32 U6.35@2550.76,-3306.15
NetR29_2: R29.2 R30.1 U6.28 | length 308.7
  Top Layer w8: R29.2@2376,-3093.35 R29.2@2376,-3093 R30.1@2376,-3038 ; v3(2481,-3068) 2481,-3129.44 2519.91,-3168.35 U6.28@2550.76,-3168.35
  Bottom Layer w8: v3(2376,-3065.52) 2478.52,-3065.52 v3(2481,-3068)
NetR39_2: R39.2 U9.3 | length 230.4
  Top Layer w8: U9.3@153.54,-3464.28 149.82,-3460.57 149.82,-3244.18 R39.2@156,-3238
NetR40_1: R40.1 R41.1 U9.7 | length 245
  Top Layer w8: R40.1@6,-3238 6,-3263 47.46,-3304.46 47.46,-3460.57 U9.7@43.74,-3464.28
NetR41_2: R41.2 R42.1 R44.1 U9.4 | length 284.6
  Top Layer w8: R44.1@56,-3238 R42.1@106,-3238 ; R42.1@101,-3243 R41.2@101,-3328 101,-3363 124.23,-3386.23 U9.4@124.23,-3468
NetR43_1: R43.1 U9.10 | length 236.1
  Top Layer w10: R43.1@-44,-3238 -44,-3303 -29.32,-3317.68 U9.10@-29.32,-3468
NetR45_2: R45.2 U10.2 U10.3 | length 90
  Top Layer w18: 1272.41,-2644 R45.2@1272.41,-2554
NetR46_2: R46.2 R47.2 | length 49
  Top Layer w15: R46.2@1496,-2567 R47.2@1496,-2518
NetR51_2: R51.2 R52.2 | length 56
  Top Layer w15: R51.2@681,-2579 681,-2573 R52.2@681,-2523
NetR56_2: R56.2 U10.12 | length 311.8
  Top Layer w8: R56.2@851,-2498 851,-2538 866,-2553 1016,-2553 1029.5,-2566.5 U10.12@1029.5,-2648
NetR58_2: R58.2 R59.2 U2.4 | length 169.5
  Top Layer w12: U2.4@5331.09,-1619.4 5373.6,-1619.4 5404,-1589 R59.2@5432,-1589 R58.2@5432,-1645
NetR114_1: R114.1 U25.12 | length 131.5
  Top Layer w8: R114.1@1954,-1274 R114.1@1959,-1279
  Top Layer w12: R114.1@1959,-1279 U25.12@2083.41,-1279
NetR115_1: R115.1 U25.10 | length 129.4
  Top Layer w12: R115.1@1954,-1179 U25.10@2083.41,-1179
NetR116_1: R116.1 U25.5 | length 135
  Top Layer w12: U25.5@2359,-1179 R116.1@2494,-1179
NRST_E: D33.2 J2.95 K1.3 K1.4 P9.1 | length 2575.2
  Top Layer w10: J2.95@4286,-899 4286,-926 4298,-938 v1(4303,-938) ; v1@4553,-939 4697,-939 4711.95,-924.05 K1.4@4711.95,-878.98 ; K1.3@4711,-1126.07 v3(4711,-1078) ; K1.3@4711.95,-1127.02 4711.95,-1293.95 4746,-1328 5534,-1328 5575,-1369 5575,-1501 5637,-1563 5824,-1563 5856,-1595 P9.1@5856,-1818
  Bottom Layer w10: v1@4304,-939 4687,-939 4711,-963 v3(4711,-1078)
  other v1: 4552,-939
ONOFF: J2.96 K2.3 K2.4 | length 785.8
  Top Layer w10: J2.96@4291.31,-713.94 4291.31,-573.69 4315,-550 K2.4@4709,-550
  Top Layer w15: K2.3@4706.95,-752.02 K2.4@4706.95,-534
PCIE_RX_N: C116.1 J2.75 | length 3998.2
  Top Layer w7: C116.1@711,-1608 711,-1589 730.5,-1569.5 730.5,-1501.37 749.87,-1482 3887,-1482 3931,-1438 3931,-1133 3921,-1123 3831,-1123 v1(3791,-1083) ; v1(3793,-931) J2.75@3793,-890
  Bottom Layer w7: v1(3791,-1083) v1@3791,-933
PCIE_RX_P: C117.1 J2.73 | length 4052.9
  Top Layer w7: C117.1@766,-1608 766,-1589 746.5,-1569.5 746.5,-1508 756.5,-1498 3893.63,-1498 3947,-1444.63 3947,-1126.37 3927.63,-1107 3850,-1107 3796,-1053 v1(3746,-1053) ; v1@3747,-927 v1(3747,-926) J2.73@3747,-886
  Bottom Layer w7: v1(3746,-1053) 3746,-1040 3747,-1039 v1(3747,-926)
PCIE_RXO_N: C116.2 J21.23 | length 556
  Top Layer w8: C116.2@709,-1673 709,-1734 684,-1759 684,-1954 841,-2111 J21.23@841,-2152 ; J21.23@841.97,-2169.4 J21.23@842,-2171
PCIE_RXO_P: C117.2 J21.25 | length 577.9
  Top Layer w8: C117.2@765,-1668 765,-1722 704,-1783 704,-1939 873,-2108 J21.25@873,-2149 ; J21.25@872,-2171 J21.25@872.02,-2169.41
